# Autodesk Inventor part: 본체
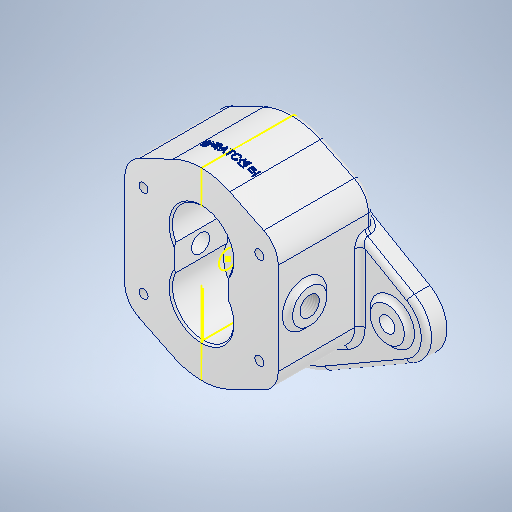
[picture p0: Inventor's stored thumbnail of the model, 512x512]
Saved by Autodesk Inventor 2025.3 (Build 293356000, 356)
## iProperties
Created: 2025-11
Part Number: 본체
Material: 알루미늄 6061
Document SubType Name: Modeling
Designer: PC-15
Density: 2.7 g/cm^3
Appearance: 알루미늄 - 평지
Mass: 1270.4 g
Surface Area: 590.969 cm^2
Volume: 470.52 cm^3
Author: PC-15
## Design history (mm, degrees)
sketch "스케치1" dims "d17" = 76
  geometry: L1 (-45, -27)-(45, -27); L2 (45, -27)-(45, 27); L3 (45, 27)-(-45, 27); L4 (-45, 27)-(-45, -27); L5 (-45, -27)-(45, 27); L6 (45, -27)-(-45, 27); L7 (0, 0)-(0, 16); L8 (0, 0)-(0, -16); L9 (0, 0)-(45, 0); L10 (36.553, 40.493)-(16.6, 50.183); L11 (-36.553, 40.493)-(-16.6, 50.183); L12 (-36.553, -40.493)-(-16.6, -50.183); L13 (36.553, -40.493)-(16.6, -50.183); C1 r 38 at (0, -16); C2 r 15 at (-30, 27); C3 r 15 at (-30, -27); C4 r 15 at (30, -27); A1 r 15 centre (30, 27) between (45, 27) and (36.553, 40.493); 12 further points
  constraints: 26 end point, 9 symmetric about line, 5 centre point, 5 midpoint, 2 coincident, 2 parallel, 2 point on circle, 2 vertical, 1 horizontal, 1 perpendicular, 1 point on line, 1 tangent, 7 other
  dimensions: "d13" = 54 distance of L1.end L2.end; "d14" = 90 distance of L2.end L3.end; "d16" = 16 distance of L7.start L7.end; "d22" = 16 distance of L7.start L8.end; "d23" = 76 diameter of C1; "d25" = 30 diameter of A1
extrude "돌출1" new body sketch "스케치1" distance "d26" = 48; taper "d27" = 0 deg
sketch "스케치2" dims "d31" = 40
  geometry: L1 (0, 0)-(0, -16); L2 (45, 27)-(45, -27) reference; L3 (36.553, -40.493)-(16.6, -50.183) reference; L4 (-16.6, -50.183)-(-36.553, -40.493) reference; L5 (-45, -27)-(-45, 27) reference; L6 (-36.553, 40.493)-(-16.6, 50.183) reference; L7 (16.6, 50.183)-(36.553, 40.493) reference; L8 (0, -16)-(-84, -16); L9 (0, -16)-(0, -54); L10 (0, -16)-(84, -16); L11 (74, 1.321)-(26, 29.033); L12 (74, -33.321)-(26, -61.033); L13 (-74, -33.321)-(-26, -61.033); L14 (-74, 1.321)-(-26, 29.033); A1 r 15 centre (30, 27) between (45, 27) and (36.553, 40.493) reference; A2 r 15 centre (30, -27) between (36.553, -40.493) and (45, -27) reference; A3 r 38 centre (0, -16) between (-16.6, -50.183) and (16.6, -50.183) reference; A4 r 15 centre (-30, -27) between (-45, -27) and (-36.553, -40.493) reference; A5 r 15 centre (-30, 27) between (-36.553, 40.493) and (-45, 27) reference; A6 r 38 centre (0, 16) between (16.6, 50.183) and (-16.6, 50.183) reference; A7 r 52 centre (0, -16) between (26, -61.033) and (26, 29.033); A8 r 20 centre (64, -16) between (84, -16) and (74, -33.321); 5 further points
  constraints: 16 end point, 6 point on circle, 6 symmetric about line, 4 tangent, 2 centre point, 2 point on line, 1 coincident, 1 horizontal, 1 vertical, 4 other
  dimensions: "d28" = 16 distance of L1.start L1.end; "d29" = 84 distance of L8.start L8.end; "d30" = 104 diameter of A7
extrude "돌출2" join sketch "스케치2" distance "d32" = 12; taper "d33" = 0 deg
sketch "스케치3"
  geometry: C1 r 10 at (64, -16); C2 r 10 at (-64, -16); A1 r 20 centre (-64, -16) between (-74, 1.321) and (-74, -33.321) reference; A2 r 20 centre (64, -16) between (74, -33.321) and (74, 1.321) reference; 1 further point
  constraints: 2 centre point, 2 coincident
  dimensions: "d34" = 20 diameter of C2; "d35" = 20 diameter of C1
extrude "돌출3" join sketch "스케치3" distance "d36" = 3; taper "d37" = 0 deg
sketch "스케치4"
  geometry: C1 r 10 at (0, 0) reference; C2 r 4.5 at (0, 0); C3 r 10 at (-128, 0) reference; C4 r 4.5 at (-128, 0); 1 further point
  constraints: 2 centre point, 2 coincident
  dimensions: "d38" = 9 diameter of C4; "d39" = 9 diameter of C2
extrude "돌출4" cut sketch "스케치4" extent not by distance; stored distance "d40" = 0; taper "d41" = 0 deg
sketch "스케치5" dims "d42" = 36, "d43" = 36
  geometry: L1 (16, 7.754)-(16, -7.754); L2 (0, 0)-(0, -16); L3 (-16, 7.754)-(-16, -7.754); A1 r 38 centre (0, 16) between (16.6, 50.183) and (-16.6, 50.183) reference; A2 r 38 centre (0, -16) between (-16.6, -50.183) and (16.6, -50.183) reference; 3 further points
  constraints: 6 end point, 2 coincident, 2 symmetric about line, 2 vertical, 6 other
  dimensions: "d44" = 16 distance from line of L1 L2.start
extrude "돌출5" cut sketch "스케치5" distance "d45" = 31; taper "d46" = 0 deg
sketch "스케치7"
  geometry: C1 r 25 at (0, -16); A1 r 52 centre (0, -16) between (-26, -61.033) and (26, -61.033) reference; 1 further point
  constraints: 1 centre point, 1 coincident
  dimensions: "d49" = 50 diameter of C1
extrude "돌출6" join sketch "스케치7" distance "d50" = 4; taper "d51" = 0 deg
sketch "스케치8"
  geometry: L1 (26, 29.033)-(45, 18.064) reference; L2 (45, 27)-(45, 18.064) reference; L3 (16.6, 50.183)-(36.553, 40.493) reference; L4 (-36.553, 40.493)-(-16.6, 50.183) reference; L5 (-45, 18.064)-(-45, 27) reference; L6 (-45, 18.064)-(-26, 29.033) reference; A1 r 15 centre (30, 27) between (45, 27) and (36.553, 40.493) reference; A2 r 38 centre (0, 16) between (16.6, 50.183) and (-16.6, 50.183) reference; A3 r 15 centre (-30, 27) between (-36.553, 40.493) and (-45, 27) reference; A4 r 52 centre (0, -16) between (26, 29.033) and (-26, 29.033) reference; 1 further point
extrude "돌출7" join sketch "스케치8" distance "d52" = 8; taper "d53" = 0 deg
sketch "스케치9"
  geometry: L1 (-68, -12)-(-68, 0) reference; L2 (-68, 0)-(-54, 0) reference; L3 (-54, 0)-(-54, 48) reference; L4 (-54, 48)-(-34, 48) reference; L5 (-34, 48)-(-34, 17) reference; L6 (-34, 17)-(34, 17) reference; L7 (34, 17)-(34, 48) reference; L8 (34, 48)-(54, 48) reference; L9 (54, 48)-(54, -8) reference; L10 (54, -8)-(36, -8) reference; L11 (36, -8)-(36, -12) reference; L12 (36, -12)-(9, -12) reference; L13 (9, -12)-(9, -16) reference; L14 (9, -16)-(-41, -16) reference; L15 (-41, -16)-(-41, -12) reference; L16 (-41, -12)-(-68, -12) reference; L17 (-68, -12)-(-68, 0) reference; L18 (-68, 0)-(-54, 0) reference; L19 (-54, 0)-(-54, 48) reference; L20 (-54, 48)-(-34, 48) reference; L21 (-34, 48)-(-34, 17) reference; L22 (-34, 17)-(34, 17) reference; L23 (34, 17)-(34, 48) reference; L24 (34, 48)-(54, 48) reference; L25 (54, 48)-(54, -8) reference; L26 (54, -8)-(36, -8) reference; L27 (36, -8)-(36, -12) reference; L28 (36, -12)-(9, -12) reference; L29 (9, -12)-(9, -16) reference; L30 (9, -16)-(-41, -16) reference; L31 (-41, -16)-(-41, -12) reference; L32 (-41, -12)-(-68, -12) reference; L33 (-68, -12)-(-68, 0) reference; L34 (-68, 0)-(-54, 0) reference; L35 (-54, 0)-(-54, 48) reference; L36 (-54, 48)-(-34, 48) reference; L37 (-34, 48)-(-34, 17) reference; L38 (-34, 17)-(34, 17) reference; L39 (34, 17)-(34, 48) reference; L40 (34, 48)-(54, 48) reference; L41 (54, 48)-(54, -8) reference; L42 (54, -8)-(36, -8) reference; L43 (36, -8)-(36, -12) reference; L44 (36, -12)-(9, -12) reference; L45 (9, -12)-(9, -16) reference; L46 (9, -16)-(-41, -16) reference; L47 (-41, -16)-(-41, -12) reference; L48 (-41, -12)-(-68, -12) reference; L49 (7.754, 48)-(7.754, 17) reference; L50 (-7.754, 48)-(-7.754, 17) reference; L51 (27, 48)-(-27, 48) reference; L52 (0, 48)-(0, -16); L53 (-7.754, 16)-(-7.754, 2); L54 (-7.754, 2)-(-19.254, 2); L55 (-19.254, 17)-(-19.254, -16); L56 (-4.254, -16)-(-4.254, -9); L57 (-4.554, -8.7)-(-19.254, -8.7); L58 (-8.754, 2)-(-8.754, -8.7); L59 (7.754, 16)-(7.754, 2); L60 (7.754, 2)-(19.254, 2); L61 (19.254, 17)-(19.254, -12); L62 (6.754, 17)-(-6.754, 17); L63 (7.754, 16)-(6.754, 17); L64 (-6.754, 17)-(-7.754, 16); A1 r 0.3 centre (-4.554, -9) between (-4.254, -9) and (-4.554, -8.7); 8 further points
  constraints: 26 end point, 17 point on line, 7 perpendicular, 3 vertical, 2 point on circle, 2 tangent, 1 centre point, 1 collinear, 1 midpoint
  dimensions: "d54" = 15 distance of L50.end L53.end; "d56" = 11.5 distance of L53.end L54.end; "d57" = 30 diameter of L56 L55; "d58" = 7.3 distance of L56.start point (-4.254, -8.7); "d59" = 21 diameter of L58 L55; "d60" = 0.3 radius of A1; "d61" = 11.5 distance of L59.end L60.end; "d62" = 15 distance of L49.end L59.end; "d63" = 1 distance of L59.start L49.end; "d64" = 1 distance of L62.start L49.end (= d63); "d65" = 1 distance of L62.end L50.end (= d63); "d66" = 1 distance of L53.start L50.end (= d65)
  node "절단 모서리 투영4"
  node "절단 모서리 투영5"
  node "절단 모서리 투영6"
revolve "회전2" stored, may be unused: angle "d68" = 90 deg
sketch "스케치10"
  geometry: 1 further point
revolve "회전3" stored, may be unused: angle "d69" = 90 deg
sketch "스케치11"
  geometry: 1 further point
sketch "스케치12"
  geometry: 5 further points
  constraints: 2 vertical alignment
  dimensions: "d70" = 54 distance of point (34, -27) point (34, 27); "d71" = 27 vertical distance of point (0, 0) point (34, 27); "d72" = 34 horizontal distance of point (0, 0) point (34, 27); "d73" = 68 distance of point (34, 27) point (-34, 27); "d74" = 54 distance of point (-34, 27) point (-34, -27); "d75" = 27 vertical distance of point (0, 0) point (-34, 27)
hole "구멍1" sketch "스케치12" at (34, 27), (34, -27), (-34, 27), (-34, -27) diameter "d76" = 5.24223; stored, may be unused: countersink angle "d80" = 90 deg, drill point angle "d82" = 118 deg; dims "d77" = 12, "d78" = 4, "d79" = 2, "d81" = 14
sketch "스케치13"
  geometry: L1 (0, 0)-(0, 54) reference; L2 (60, -23.064)-(48, -23.064) reference; L3 (48, -23.064)-(48, 0) reference; L4 (48, 0)-(48, 45.064) reference; L5 (48, 45.064)-(56, 45.064) reference; L6 (56, 45.064)-(60, 45.064) reference; L7 (60, 45.064)-(60, -23.064) reference; L8 (48, 0)-(0, 0) reference; L9 (0, 0)-(0, 54) reference; L10 (56, 54)-(0, 54) reference; L11 (56, 54)-(56, 45.064) reference; L12 (0, 34.754)-(31, 34.754) reference; C1 r 10 at (15.5, 27); 3 further points
  constraints: 2 midpoint, 1 centre point, 1 horizontal alignment, 1 vertical alignment
  dimensions: "d83" = 20 diameter of C1
extrude "돌출8" join sketch "스케치13" distance "d84" = 3; taper "d85" = 0 deg
sketch "스케치14"
  geometry: C1 r 10 at (0, 0) reference; 1 further point
hole "구멍2" sketch "스케치14" at (0, 0) diameter "d86" = 10.5; stored, may be unused: countersink angle "d92" = 90 deg, drill point angle "d94" = 118 deg; dims "d87" = 11, "d88" = 0.62479, "d89" = 10.589, "d90" = 4, "d91" = 2, "d93" = 39.25
fillet "모깎기1" dims "d95" = 3
chamfer "모따기1" distance "d96" = 1; stored, may be unused: second distance "d97" = 2, angle "d98" = 45 deg
fillet "모깎기2" dims "d99" = 3
fillet "모깎기3" dims "d100" = 3
sketch "스케치15"
  geometry: L1 (-16.6, 48)-(-36.553, 48) reference; L2 (17.91, 0)-(-17.91, 0) reference; 3 further points
  constraints: 1 coincident, 1 midpoint, 1 vertical alignment, 1 other
  dimensions: "d101" = 16 distance from line of L1 point (0, 32)
feature "엠보싱1" sketch "스케치15" dims "d13" = 54, "d14" = 90, "d16" = 16, "d17" = 76, "d25" = 30, "d102" = 0.5, "d103" = 0
sketch "스케치16"
  geometry: L1 (-34.254, -9)-(-34.254, -16) reference; L2 (-34.254, -16)-(-41, -16) reference; L3 (-41, -16)-(-41, -15) reference; L4 (-44, -12)-(-68, -12) reference; L5 (-68, -12)-(-68, -3) reference; L6 (-65, 0)-(-57, 0) reference; L7 (-54, 3)-(-54, 48) reference; L8 (-54, 48)-(-35, 48) reference; L9 (-35, 48)-(-34, 47) reference; L10 (-34, 47)-(-34, 17) reference; L11 (-34, 17)-(-31.754, 17) reference; L12 (-31.754, 17)-(-30.754, 16) reference; L13 (-30.754, 16)-(-30.754, 2) reference; L14 (-30.754, 2)-(-29.754, 2) reference; L15 (-29.754, 2)-(-29.754, -8.7) reference; L16 (-29.754, -8.7)-(-33.954, -8.7) reference; L17 (30.754, 2)-(30.754, 16) reference; L18 (30.754, 16)-(31.754, 17) reference; L19 (31.754, 17)-(34, 17) reference; L20 (34, 17)-(34, 47) reference; L21 (34, 47)-(35, 48) reference; L22 (35, 48)-(54, 48) reference; L23 (54, 48)-(54, 30.423) reference; L24 (54, 30.423)-(54.5, 30.423) reference; L25 (54.5, 30.423)-(54.5, 30.092) reference; L26 (54.5, 30.092)-(54, 30.092) reference; L27 (54, 30.092)-(54, -5) reference; L28 (51, -8)-(39, -8) reference; L29 (36, -11)-(36, -12) reference; L30 (36, -12)-(12, -12) reference; L31 (9, -15)-(9, -16) reference; L32 (9, -16)-(-4.254, -16) reference; L33 (-4.254, -16)-(-4.254, -9) reference; L34 (-4.554, -8.7)-(-8.754, -8.7) reference; L35 (-8.754, -8.7)-(-8.754, 2) reference; L36 (-8.754, 2)-(-7.754, 2) reference; L37 (-7.754, 2)-(-7.754, 16) reference; L38 (-7.754, 16)-(-6.754, 17) reference; L39 (-6.754, 17)-(6.754, 17) reference; L40 (6.754, 17)-(7.754, 16) reference; L41 (7.754, 16)-(7.754, 2) reference; L42 (7.754, 2)-(30.754, 2) reference; L43 (-34, 47)-(-7.754, 47) reference; L44 (-5.753, 48)-(-35, 48) reference; C1 r 5.25 at (0, 32.5) reference; A1 r 3 centre (-44, -15) between (-41, -15) and (-44, -12) reference; A2 r 3 centre (-65, -3) between (-65, 0) and (-68, -3) reference; A3 r 3 centre (-57, 3) between (-57, 0) and (-54, 3) reference; A4 r 0.3 centre (-33.954, -9) between (-33.954, -8.7) and (-34.254, -9) reference; A5 r 3 centre (51, -5) between (51, -8) and (54, -5) reference; A6 r 3 centre (39, -11) between (39, -8) and (36, -11) reference; A7 r 3 centre (12, -15) between (12, -12) and (9, -15) reference; A8 r 0.3 centre (-4.554, -9) between (-4.254, -9) and (-4.554, -8.7) reference; 1 further point
  node "절단 모서리 투영8"
chamfer "모따기2" distance "d104" = 0.7; stored, may be unused: second distance "d105" = 2, angle "d106" = 30 deg
node "솔리드1"
mirror "미러1"
node "절단 모서리 투영1"
node "절단 모서리 투영7"
feature "A9D066F2-1C7D-4E18-AEED-F7BC21143FA4" dims "d76" = 5.24223, "d77" = 12, "d78" = 4, "d79" = 2, "d80" = 90 deg, "d81" = 14, "d82" = 118 deg
